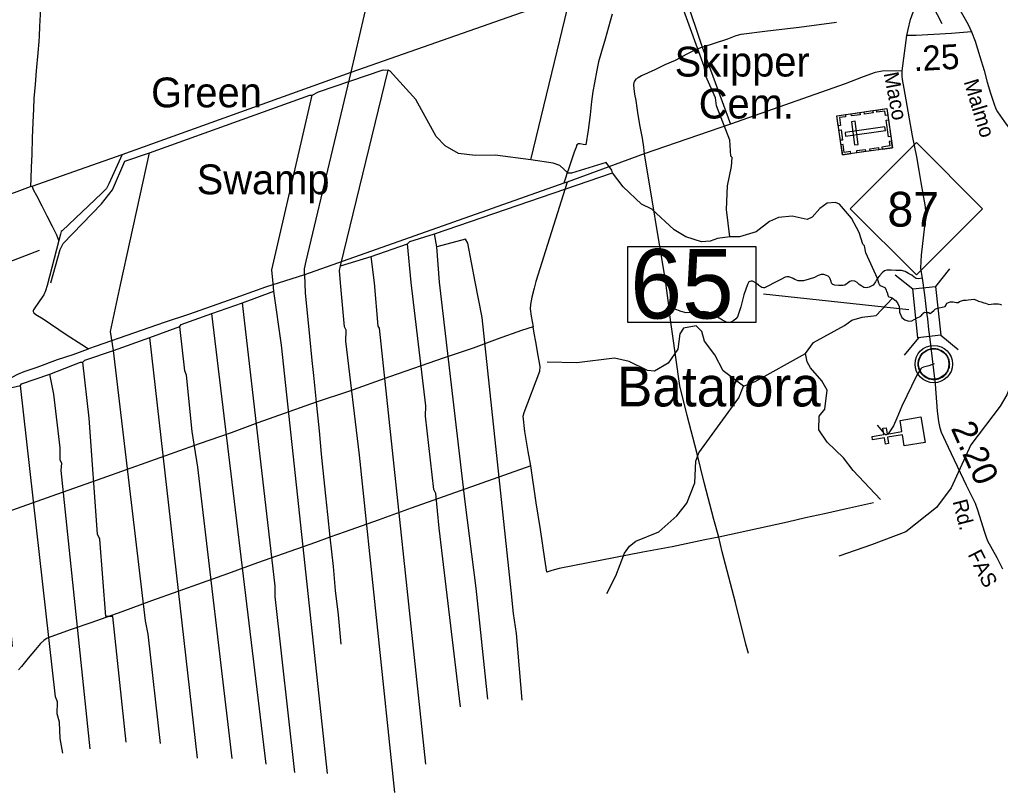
# Model space of a CAD drawing. Extents: x 2225501 to 2309677, y 165449 to 227696.
# Drawn here: x 2240180 to 2259935, y 172803 to 188364 of the extents above; entities that cross this region are included whole.
import ezdxf

# ---------------------------------------------------------------- set-up
doc = ezdxf.new("R2010")
doc.units = 0
for name, color, linetype in [('Exist Vegetation Text', 7, 'Continuous'), ('MARK ENDS WORD SYMBOL CELL', 7, 'Continuous'), ('Old_Level_3', 7, 'Continuous'), ('Old_Level_33', 7, 'Continuous'), ('Old_Level_50', 7, 'Continuous'), ('P_HYD_Default', 7, 'Continuous'), ('P_HYD_Diversion_Ditch_Label', 7, 'Continuous'), ('P_HYD_Drop_Inlet_Grate_2_Narrow_Slots_and_Sag_Grates_840_24_54_Dia_CELL', 7, 'Continuous'), ('P_HYD_Drop_Inlet_Grate_3_Narrow_Slot_and_Sag_Grates_840_22_Type_A_60_Dia-Top_CELL', 7, 'Continuous'), ('P_HYD_Endwall_838_01_18_Dia_Single-Top_CELL', 7, 'Continuous'), ('P_HYD_Endwall_838_01_30_Dia_Single-Top_CELL', 7, 'Continuous'), ('P_HYD_Endwall_838_01_30_Dia_Single_CELL', 7, 'Continuous'), ('P_HYD_Junction_Box_with_Slab_Lid_840_31_15_Dia-Top_CELL', 7, 'Continuous'), ('P_HYD_RipRap_Pad_876_02_18in_Outlet_With_Ditch_CELL', 7, 'Continuous'), ('P_RDY_Dimension_Text', 7, 'Continuous'), ('Prop Mkg Solid Yellow Edge Line', 7, 'Continuous'), ('Prop Support', 7, 'Continuous'), ('Scratch_Level_5', 7, 'Continuous'), ('Scratch_Level_7', 7, 'Continuous'), ('Typical Terminator CELL', 7, 'Continuous')]:
    doc.layers.add(name, color=color, linetype=linetype)

msp = doc.modelspace()

# ---------------------------------------------------------------- linework, layer by layer
at = {"layer": 'Old_Level_3'}
for p, q in [((2246857, 187307), (2247595, 190467)), ((2253221, 189916), (2253929, 187812)), ((2253929, 187812), (2254499, 186260)), ((2242243, 185650), (2246857, 187307)), ((2254499, 186260), (2252763, 185662)), ((2240431, 185013), (2242243, 185650)), ((2252763, 185662), (2251208, 185093)), ((2238902, 184451), (2240402, 185003)), ((2240402, 185003), (2240431, 185013)), ((2251139, 185069), (2245917, 183225)), ((2251208, 185093), (2251139, 185069))]:
    msp.add_line(p, q, dxfattribs=at)
for points in [[(2246857, 187307), (2252397, 189255), (2252411, 189261)], [(2240609, 188826), (2240606, 188700), (2240594, 188470), (2240583, 188226), (2240577, 188031), (2240568, 187924), (2240545, 187694), (2240513, 187333), (2240490, 187057), (2240466, 186774), (2240458, 186565), (2240446, 186294), (2240434, 185986), (2240423, 185651), (2240414, 185395), (2240405, 185160), (2240402, 185003)], [(2252118, 188474), (2252077, 188334), (2252042, 188212), (2251972, 187968), (2251902, 187723), (2251838, 187514), (2251804, 187345), (2251757, 187089), (2251728, 186920), (2251699, 186717), (2251670, 186449), (2251629, 186135), (2251588, 185844), (2251530, 185850), (2251472, 185861), (2251437, 185861), (2251402, 185844), (2251391, 185797), (2251350, 185692), (2251292, 185516), (2251228, 185333), (2251204, 185263), (2251181, 185192), (2251139, 185069)], [(2253929, 187812), (2254443, 187980), (2254610, 188044), (2254712, 188069), (2255241, 188141), (2255882, 188214), (2256635, 188312)], [(2253929, 187812), (2253767, 187742), (2253621, 187666), (2253383, 187544), (2253173, 187451), (2252976, 187352), (2252842, 187294), (2252708, 187230), (2252638, 187195), (2252595, 187165), (2252563, 187124), (2252551, 187095), (2252545, 187048), (2252551, 186978), (2252568, 186865), (2252589, 186734), (2252609, 186591), (2252635, 186446), (2252673, 186212), (2252717, 185979), (2252746, 185796), (2252763, 185662)], [(2245917, 183225), (2245920, 183343), (2245953, 183501), (2246857, 187307)], [(2257957, 187330), (2257553, 187326), (2257489, 187316), (2257413, 187297), (2257172, 187211), (2256805, 187074), (2254499, 186260)], [(2242243, 185650), (2241980, 185058), (2241930, 184966), (2241833, 184871), (2241034, 184112), (2241020, 184096), (2241002, 184042), (2240969, 183913)], [(2252763, 185662), (2253182, 183110), (2253252, 182606)], [(2240969, 183913), (2240932, 184022), (2240842, 184197), (2240734, 184403), (2240632, 184607), (2240525, 184819), (2240466, 184925), (2240431, 185013)], [(2251208, 185093), (2250576, 183088), (2250542, 182954), (2250500, 182776), (2250469, 182627), (2250464, 182537), (2250486, 182395), (2250525, 182178)], [(2240969, 183913), (2240733, 183009), (2240704, 182901), (2240671, 182824), (2240584, 182706), (2240461, 182517), (2240456, 182501), (2240454, 182487), (2240457, 182471), (2240464, 182463), (2240510, 182429), (2240653, 182340), (2241120, 182025), (2241433, 181825), (2241568, 181734)], [(2245917, 183225), (2245131, 182974), (2244611, 182787), (2243604, 182432), (2243094, 182264), (2241722, 181786), (2241568, 181734)], [(2245917, 183225), (2245932, 182865), (2246022, 181980), (2246067, 181499), (2246101, 181197), (2246152, 180661)], [(2258363, 183156), (2258278, 183146), (2258241, 183152), (2258196, 183177), (2258152, 183215), (2258087, 183255), (2258019, 183292), (2257944, 183309), (2257831, 183312), (2257735, 183321), (2257645, 183322), (2257603, 183308), (2257553, 183262), (2257502, 183202), (2257451, 183152), (2257417, 183083), (2257373, 183020), (2257294, 182974), (2257238, 182960), (2257186, 182972), (2257145, 182995), (2257093, 183030), (2257052, 183071), (2257005, 183100), (2256941, 183106), (2256901, 183094), (2256848, 183052), (2256802, 183020), (2256764, 183011), (2256674, 183011), (2256601, 183020), (2256558, 183032), (2256534, 183058), (2256523, 183090), (2256505, 183142), (2256491, 183174), (2256467, 183195), (2256432, 183212), (2256380, 183232), (2256328, 183232), (2256264, 183212), (2256188, 183171), (2256081, 183136), (2255967, 183107), (2255906, 183104), (2255860, 183104), (2255796, 183128), (2255761, 183151), (2255717, 183170), (2255676, 183187), (2255636, 183184), (2255602, 183180), (2255513, 183129), (2255380, 183067), (2255263, 183001), (2255185, 182963), (2255162, 182961), (2255131, 182972), (2255071, 183009), (2255018, 183057), (2254970, 183086), (2254942, 183096), (2254912, 183099), (2254891, 183094), (2254870, 183081), (2254841, 183028), (2254767, 182822), (2254708, 182579), (2254640, 182378), (2254606, 182336), (2254563, 182303), (2254492, 182268), (2254457, 182265), (2254415, 182274), (2254335, 182309), (2254119, 182448), (2254047, 182473), (2253947, 182484), (2253787, 182466), (2253605, 182460), (2253505, 182489), (2253362, 182539), (2253252, 182606)], [(2254263, 177942), (2254165, 178297), (2253970, 179043), (2253818, 179649), (2253624, 180393), (2253481, 180993), (2253252, 182606)], [(2250525, 182178), (2250292, 182101), (2249800, 181927), (2249314, 181750), (2248734, 181555), (2247631, 181172), (2246802, 180876), (2246152, 180661)], [(2250478, 179378), (2250422, 179667), (2250356, 180068), (2250320, 180378), (2250341, 180452), (2250655, 181288), (2250664, 181382), (2250623, 181601), (2250580, 181873), (2250546, 182048), (2250525, 182178)], [(2238274, 180258), (2239096, 180681), (2239691, 180992), (2240141, 181224), (2240270, 181277), (2240534, 181367), (2240942, 181517), (2241257, 181624), (2241568, 181734)], [(2258599, 181435), (2258496, 181394), (2258386, 181364), (2258350, 181350), (2258331, 181332), (2258248, 181189), (2257947, 180583), (2257848, 180338), (2257780, 180181), (2257672, 180022), (2257642, 180004), (2257622, 180001), (2257594, 180021), (2257565, 180067), (2257458, 180198)], [(2246152, 180661), (2244980, 180243), (2244438, 180046), (2243796, 179825), (2241836, 179122), (2240831, 178769), (2240432, 178625), (2239920, 178447), (2239537, 178309), (2239230, 178206), (2239051, 178137), (2238909, 178086)], [(2246152, 180661), (2246170, 180464), (2246211, 180082), (2246255, 179611), (2246343, 178772), (2246384, 178400), (2246430, 177945)], [(2250478, 179378), (2248064, 178523), (2247405, 178286), (2246737, 178050), (2246430, 177945)], [(2250799, 177238), (2250756, 177499), (2250671, 178094), (2250585, 178637), (2250478, 179378)], [(2257382, 178637), (2256836, 178514), (2256393, 178411), (2256008, 178333), (2255647, 178246), (2254263, 177942)], [(2246430, 177945), (2246137, 177836), (2244969, 177424), (2244369, 177204), (2243857, 177026), (2243368, 176850), (2242834, 176661), (2242240, 176442), (2241614, 176214), (2241221, 176083), (2240737, 175906), (2240667, 175864), (2240598, 175801), (2240503, 175682), (2240354, 175507), (2240220, 175340), (2240159, 175269)], [(2246430, 177945), (2246496, 177353), (2246538, 176866), (2246593, 176376), (2246652, 175787)], [(2254263, 177942), (2253981, 177887), (2253323, 177749), (2252736, 177640), (2251046, 177309), (2250903, 177271), (2250799, 177238)], [(2254860, 175599), (2254806, 175789), (2254600, 176628), (2254332, 177649), (2254263, 177942)]]:
    msp.add_lwpolyline(points, dxfattribs=at)
at = {"layer": 'Old_Level_33'}
for points in [[(2258446, 191137), (2258544, 191029), (2258600, 190962), (2258694, 190839), (2258749, 190765), (2258807, 190686), (2258826, 190657), (2258840, 190623), (2258865, 190541), (2258887, 190273), (2258898, 190049), (2258916, 189770), (2258921, 189522), (2258922, 189349), (2258928, 189149), (2258936, 189033), (2258958, 188914), (2258977, 188847), (2259010, 188773), (2259044, 188693), (2259093, 188605), (2259173, 188467), (2259289, 188266), (2259355, 188119)], [(2259355, 188119), (2258950, 188085), (2258238, 188043), (2258048, 188045)], [(2259355, 188119), (2259430, 187933), (2259522, 187620), (2259608, 187337), (2259668, 187105), (2259737, 186885), (2259808, 186664), (2259842, 186567), (2259875, 186505), (2260016, 186307), (2260694, 185377), (2260791, 185246), (2260894, 185106), (2261122, 184798), (2261235, 184695), (2261579, 184456), (2261731, 184382), (2261883, 184329), (2261988, 184289), (2262373, 184152), (2262470, 184111), (2262544, 184064), (2262687, 183949), (2262952, 183720)]]:
    msp.add_lwpolyline(points, dxfattribs=at)
at = {"layer": 'Old_Level_50'}
for points in [[(2258048, 188045), (2258076, 188167), (2258122, 188366), (2258175, 188511), (2258210, 188623), (2258225, 188695), (2258297, 189461), (2258331, 189995), (2258365, 190369), (2258395, 190695), (2258415, 190871), (2258446, 191137)], [(2258456, 182467), (2258435, 182645), (2258410, 182822), (2258363, 183155), (2258331, 183350), (2258336, 183498), (2258349, 183620), (2258415, 184208), (2258428, 184316), (2258435, 184383), (2258433, 184500), (2258428, 184592), (2258339, 185083), (2258301, 185323), (2258253, 185599), (2258167, 186022), (2257994, 186980), (2257960, 187161), (2257954, 187227), (2257957, 187330), (2258048, 188045)], [(2259986, 177299), (2259867, 177528), (2259683, 177863), (2259654, 177936), (2259619, 178039), (2259482, 178483), (2259431, 178617), (2259255, 178986), (2258888, 179747), (2258752, 180053), (2258721, 180134), (2258695, 180274), (2258671, 180479), (2258630, 181021), (2258584, 181422), (2258519, 181930), (2258492, 182124), (2258471, 182341), (2258456, 182467)]]:
    msp.add_lwpolyline(points, dxfattribs=at)
at = {"layer": 'P_HYD_Diversion_Ditch_Label'}
msp.add_lwpolyline([(2258283, 181478), (2258287, 181500), (2258294, 181527), (2258306, 181555), (2258317, 181578), (2258331, 181601), (2258346, 181622), (2258362, 181639), (2258380, 181658), (2258402, 181676), (2258424, 181691), (2258443, 181702), (2258464, 181712), (2258485, 181721), (2258508, 181729), (2258525, 181733), (2258545, 181736), (2258561, 181739), (2258587, 181740), (2258604, 181740), (2258627, 181739), (2258647, 181736), (2258666, 181732), (2258686, 181726), (2258707, 181718), (2258734, 181707), (2258759, 181693), (2258779, 181678), (2258800, 181662), (2258813, 181650), (2258829, 181632), (2258845, 181614), (2258857, 181595), (2258870, 181575), (2258879, 181554), (2258888, 181534), (2258894, 181514), (2258899, 181496), (2258903, 181472), (2258906, 181453), (2258907, 181429), (2258906, 181406), (2258904, 181383), (2258900, 181361), (2258893, 181337), (2258886, 181313), (2258877, 181293), (2258864, 181269), (2258851, 181248), (2258837, 181229), (2258820, 181210), (2258799, 181190), (2258779, 181174), (2258759, 181160), (2258742, 181150), (2258715, 181137), (2258686, 181126), (2258662, 181120), (2258636, 181115), (2258618, 181113), (2258600, 181112), (2258578, 181112), (2258561, 181114), (2258538, 181117), (2258514, 181122), (2258496, 181127), (2258475, 181135), (2258457, 181142), (2258441, 181151), (2258414, 181168), (2258392, 181185), (2258372, 181203), (2258354, 181222), (2258342, 181238), (2258330, 181255), (2258313, 181283), (2258306, 181297), (2258299, 181313), (2258289, 181346), (2258283, 181374), (2258280, 181395), (2258279, 181420), (2258279, 181439), (2258281, 181465)], close=True, dxfattribs=at)
for centre, radius in [((2258593, 181428), 377), ((2258592, 181429), 307)]:
    msp.add_circle(centre, radius, dxfattribs=at)
at = {"layer": 'P_HYD_Endwall_838_01_18_Dia_Single-Top_CELL'}
msp.add_lwpolyline([(2258764, 188280), (2258018, 189724), (2257273, 189702)], dxfattribs=at)
at = {"layer": 'P_HYD_Endwall_838_01_30_Dia_Single-Top_CELL'}
msp.add_line((2258091, 182521), (2255164, 182838), dxfattribs=at)
msp.add_lwpolyline([(2252431, 183795), (2255008, 183795), (2255008, 182266), (2252431, 182266)], close=True, dxfattribs=at)
at = {"layer": 'P_HYD_Endwall_838_01_30_Dia_Single_CELL'}
for p, q in [((2258913, 183346), (2258629, 182993)), ((2257816, 183228), (2258168, 182944)), ((2258283, 181959), (2257999, 181606)), ((2258733, 182007), (2259086, 181723))]:
    msp.add_line(p, q, dxfattribs=at)
msp.add_lwpolyline([(2258629, 182993), (2258735, 182008), (2258275, 181958), (2258168, 182944)], close=True, dxfattribs=at)
at = {"layer": 'P_HYD_Junction_Box_with_Slab_Lid_840_31_15_Dia-Top_CELL'}
msp.add_lwpolyline([(2256910, 184555), (2258242, 185887), (2259574, 184555), (2258242, 183223)], close=True, dxfattribs=at)
at = {"layer": 'Prop Mkg Solid Yellow Edge Line'}
for points in [[(2256752, 185640), (2256640, 186429), (2257649, 186572), (2257761, 185784)], [(2257108, 186449), (2256936, 186425), (2256930, 186470), (2257101, 186495)], [(2257369, 186486), (2257197, 186462), (2257191, 186507), (2257362, 186532)], [(2257667, 186441), (2257622, 186435), (2257609, 186522), (2257449, 186499), (2257443, 186543), (2257649, 186572)], [(2256812, 186453), (2256818, 186408), (2256691, 186390), (2256714, 186230), (2256670, 186223), (2256640, 186429)], [(2256999, 185840), (2257073, 185851), (2257007, 186317), (2256933, 186307)], [(2257683, 186005), (2257635, 186341), (2257680, 186347), (2257728, 186011)], [(2256711, 185934), (2256682, 186139), (2256727, 186145), (2256756, 185940)], [(2256807, 186089), (2256818, 186015), (2257621, 186129), (2257610, 186203)], [(2257742, 185915), (2257697, 185908), (2257709, 185821), (2257549, 185798), (2257555, 185754), (2257761, 185784)], [(2256924, 185665), (2256918, 185710), (2256790, 185691), (2256767, 185852), (2256723, 185846), (2256752, 185640)], [(2257218, 185706), (2257046, 185682), (2257040, 185727), (2257211, 185752)], [(2257484, 185744), (2257312, 185720), (2257306, 185765), (2257477, 185789)]]:
    msp.add_lwpolyline(points, close=True, dxfattribs=at)
at = {"layer": 'Prop Support'}
for p, q in [((2250476, 185539), (2251620, 190247)), ((2246645, 183406), (2247604, 187347)), ((2242210, 183024), (2242793, 185682)), ((2248539, 184048), (2252119, 185278)), ((2248582, 183788), (2248539, 184048)), ((2247259, 183594), (2247991, 183852)), ((2248064, 183072), (2247991, 183852)), ((2248639, 183077), (2248582, 183788)), ((2246645, 183406), (2247259, 183594)), ((2247331, 183066), (2247259, 183594)), ((2245301, 182894), (2245289, 183050)), ((2244669, 182664), (2245301, 182894)), ((2244055, 182443), (2244669, 182664)), ((2245145, 173372), (2244055, 182443)), ((2242800, 181966), (2243408, 182187)), ((2242069, 181701), (2242800, 181966)), ((2243761, 173494), (2242800, 181966))]:
    msp.add_line(p, q, dxfattribs=at)
for points in [[(2254487, 183988), (2254416, 184538), (2254437, 185019), (2254517, 185405), (2254532, 185588), (2254507, 185612), (2254488, 185937), (2254215, 186628), (2254197, 186792), (2254002, 187226), (2253967, 187417), (2253533, 188619), (2253490, 188679), (2253413, 188953), (2253218, 189383), (2253175, 189590), (2253091, 189592), (2252528, 189213)], [(2246074, 186842), (2246200, 186912), (2247504, 187355), (2247604, 187347)], [(2250476, 185539), (2249759, 185632), (2249359, 185630), (2249017, 185666), (2248749, 185822), (2248573, 186013), (2248158, 186759), (2247646, 187323), (2247604, 187347)], [(2242793, 185682), (2246024, 186843), (2246074, 186842)], [(2245289, 183050), (2245261, 183328), (2246074, 186842)], [(2240808, 183061), (2240994, 183736), (2241060, 183853), (2241827, 184658), (2242050, 184936), (2242296, 185511), (2242793, 185682)], [(2252119, 185278), (2252110, 185334), (2251992, 185484), (2251294, 185271), (2251228, 185269), (2251060, 185426), (2250926, 185475), (2250476, 185539)], [(2254487, 183988), (2254237, 183954), (2254088, 183901), (2253913, 183891), (2253596, 183989), (2253361, 184128), (2252916, 184550), (2252707, 184650), (2252338, 184995), (2252119, 185278)], [(2257458, 183149), (2257222, 183670), (2257196, 183811), (2257162, 183845), (2257093, 184076), (2256933, 184367), (2256697, 184647), (2256614, 184679), (2256447, 184669), (2256298, 184560), (2256141, 184386), (2256042, 184342), (2255741, 184407), (2255467, 184380), (2255284, 184301), (2255019, 184093), (2254678, 183988), (2254487, 183988)], [(2247991, 183852), (2248040, 183894), (2248539, 184048)], [(2249356, 183083), (2249207, 183862), (2249164, 183944), (2248582, 183788)], [(2240577, 183715), (2239963, 183477), (2239847, 183309), (2239737, 183004)], [(2246640, 183061), (2246620, 183315), (2246645, 183406)], [(2257761, 182756), (2257721, 182766), (2257691, 182778), (2257675, 182810), (2257667, 182842), (2257649, 182886), (2257641, 182916), (2257613, 182962), (2257565, 182984), (2257521, 183004), (2257497, 183031), (2257487, 183059), (2257458, 183149)], [(2242069, 181701), (2242009, 182086), (2242210, 183024)], [(2247741, 172803), (2247027, 179594), (2246751, 181889), (2246756, 182108), (2246723, 182181), (2246640, 183061)], [(2248361, 173372), (2247431, 182154), (2247405, 182194), (2247331, 183066)], [(2249059, 174529), (2248630, 178123), (2248566, 178823), (2248524, 178899), (2248354, 180378), (2248361, 180588), (2248064, 183072)], [(2249608, 174682), (2249373, 176914), (2249151, 178654), (2248639, 183077)], [(2250300, 174662), (2250189, 176003), (2250127, 176404), (2250082, 176868), (2249496, 182363), (2249356, 183083)], [(2246380, 173180), (2245452, 181806), (2245301, 182894)], [(2245721, 173203), (2245326, 176747), (2245325, 176957), (2244669, 182664)], [(2243408, 182187), (2243432, 182222), (2244055, 182443)], [(2244461, 173483), (2243772, 179352), (2243658, 180073), (2243540, 181207), (2243507, 181289), (2243408, 182187)], [(2254763, 180982), (2254353, 181295), (2254183, 181616), (2253973, 181889), (2253921, 182081), (2253804, 182198), (2253554, 182153), (2253480, 182037), (2253441, 181729), (2253244, 181444), (2252970, 181282), (2252828, 181298), (2252460, 181479), (2252160, 181544), (2251402, 181454), (2250803, 181466)], [(2241455, 181464), (2241497, 181505), (2242069, 181701)], [(2243018, 173787), (2242767, 175986), (2242713, 176260), (2242069, 181701)], [(2254763, 180982), (2254996, 181076), (2256007, 181640)], [(2240791, 181224), (2241405, 181465), (2241455, 181464)], [(2242326, 173817), (2242055, 176345), (2241914, 176344), (2241793, 177901), (2241751, 178001), (2241582, 180339), (2241455, 181464)], [(2240201, 180996), (2240217, 181029), (2240791, 181224)], [(2241601, 173683), (2241014, 179288), (2241030, 179435), (2240997, 179495), (2240995, 179744), (2240869, 180819), (2240791, 181224)], [(2240036, 175738), (2239570, 180707), (2240026, 180954), (2240201, 180996)], [(2241053, 173596), (2241000, 173889), (2240982, 174220), (2240939, 174388), (2240945, 174628), (2240902, 174730), (2240201, 180996)], [(2252006, 176811), (2252187, 177161), (2252366, 177620), (2252465, 177763), (2252589, 177865), (2253054, 178050), (2253418, 178371), (2253616, 178629), (2253779, 179039), (2253801, 179472), (2253858, 179641), (2254665, 180748), (2254763, 180982)]]:
    msp.add_lwpolyline(points, dxfattribs=at)
at = {"layer": 'Scratch_Level_5'}
msp.add_lwpolyline([(2257999, 179779), (2257962, 180004), (2257662, 179954), (2257682, 179828), (2257619, 179818), (2257599, 179944), (2257361, 179905), (2257351, 179968), (2257588, 180007), (2257568, 180134), (2257631, 180144), (2257651, 180018), (2257952, 180067), (2257915, 180294), (2258335, 180363), (2258420, 179848)], close=True, dxfattribs=at)
at = {"layer": 'Typical Terminator CELL'}
for points in [[(2256007, 181640), (2256172, 181860), (2256794, 182205), (2256943, 182314), (2257151, 182375), (2257434, 182409), (2257761, 182756)], [(2257761, 182756), (2257821, 182710), (2257861, 182658), (2257899, 182590), (2257902, 182472), (2257948, 182369), (2258013, 182321), (2258089, 182294), (2258152, 182302), (2258246, 182352), (2258333, 182395), (2258370, 182441), (2258379, 182453), (2258406, 182470), (2258470, 182467), (2258491, 182467), (2258520, 182449), (2258555, 182475), (2258592, 182505), (2258620, 182536), (2258668, 182552), (2258702, 182560), (2258764, 182572), (2258824, 182586), (2258842, 182622), (2258858, 182656), (2258923, 182680), (2258981, 182678), (2259016, 182674), (2259053, 182666), (2259082, 182670), (2259108, 182686), (2259153, 182704), (2259193, 182716), (2259245, 182718), (2259287, 182724), (2259345, 182728), (2259401, 182732), (2259453, 182714), (2259497, 182698), (2259549, 182678), (2259603, 182664), (2259635, 182656), (2259669, 182638), (2259701, 182628), (2259747, 182634), (2259797, 182638), (2259849, 182639), (2259888, 182641), (2259925, 182637), (2259954, 182621)], [(2260874, 182613), (2260706, 182286), (2260544, 182017), (2260389, 181633), (2260063, 180807), (2259931, 180580), (2259338, 179801), (2258945, 178939), (2258648, 178538), (2258028, 178052), (2257338, 177786), (2256682, 177563)], [(2257522, 178704), (2256968, 179282), (2256774, 179539), (2256447, 179854), (2256278, 180103), (2256284, 180378), (2256400, 180520), (2256447, 180903), (2256337, 181092), (2256110, 181349), (2256042, 181475), (2256007, 181640)]]:
    msp.add_lwpolyline(points, dxfattribs=at)

# ---------------------------------------------------------------- texts
at = {"layer": 'Exist Vegetation Text'}
for s, p in [('Skipper', (2253374, 187218)), ('Cem.', (2253859, 186373))]:
    msp.add_text(s, height=600, dxfattribs=at).set_placement(p)
at = {"layer": 'MARK ENDS WORD SYMBOL CELL'}
msp.add_text('Malmo', height=300, rotation=286.9387, dxfattribs=at).set_placement((2259193, 187114))
at = {"layer": 'P_HYD_Default'}
for s, p in [('Green', (2242829, 186598)), ('Swamp', (2243747, 184847))]:
    msp.add_text(s, height=600, dxfattribs=at).set_placement(p)
at = {"layer": 'P_HYD_Drop_Inlet_Grate_2_Narrow_Slots_and_Sag_Grates_840_24_54_Dia_CELL'}
for s, rotation, p in [('Maco', 280.841, (2257583, 187281)), ('Rd.', 284.5169, (2258969, 178662)), ('FAS', 296.7982, (2259269, 177594))]:
    msp.add_text(s, height=300, rotation=rotation, dxfattribs=at).set_placement(p)
at = {"layer": 'P_HYD_Drop_Inlet_Grate_3_Narrow_Slot_and_Sag_Grates_840_22_Type_A_60_Dia-Top_CELL'}
msp.add_text('Batarora', height=800, dxfattribs=at).set_placement((2252212, 180575))
at = {"layer": 'P_HYD_Endwall_838_01_30_Dia_Single-Top_CELL'}
msp.add_text('65', height=1400, dxfattribs=at).set_placement((2252481, 182345))
at = {"layer": 'P_HYD_RipRap_Pad_876_02_18in_Outlet_With_Ditch_CELL'}
msp.add_text('87', height=700, dxfattribs=at).set_placement((2257659, 184196))
at = {"layer": 'P_RDY_Dimension_Text'}
msp.add_text('.25', height=500, rotation=3.3019, dxfattribs=at).set_placement((2258193, 187323))
at = {"layer": 'Scratch_Level_7'}
msp.add_text('2.20', height=500, rotation=294.1669, dxfattribs=at).set_placement((2258930, 180138))

doc.saveas('drawing.dxf')
